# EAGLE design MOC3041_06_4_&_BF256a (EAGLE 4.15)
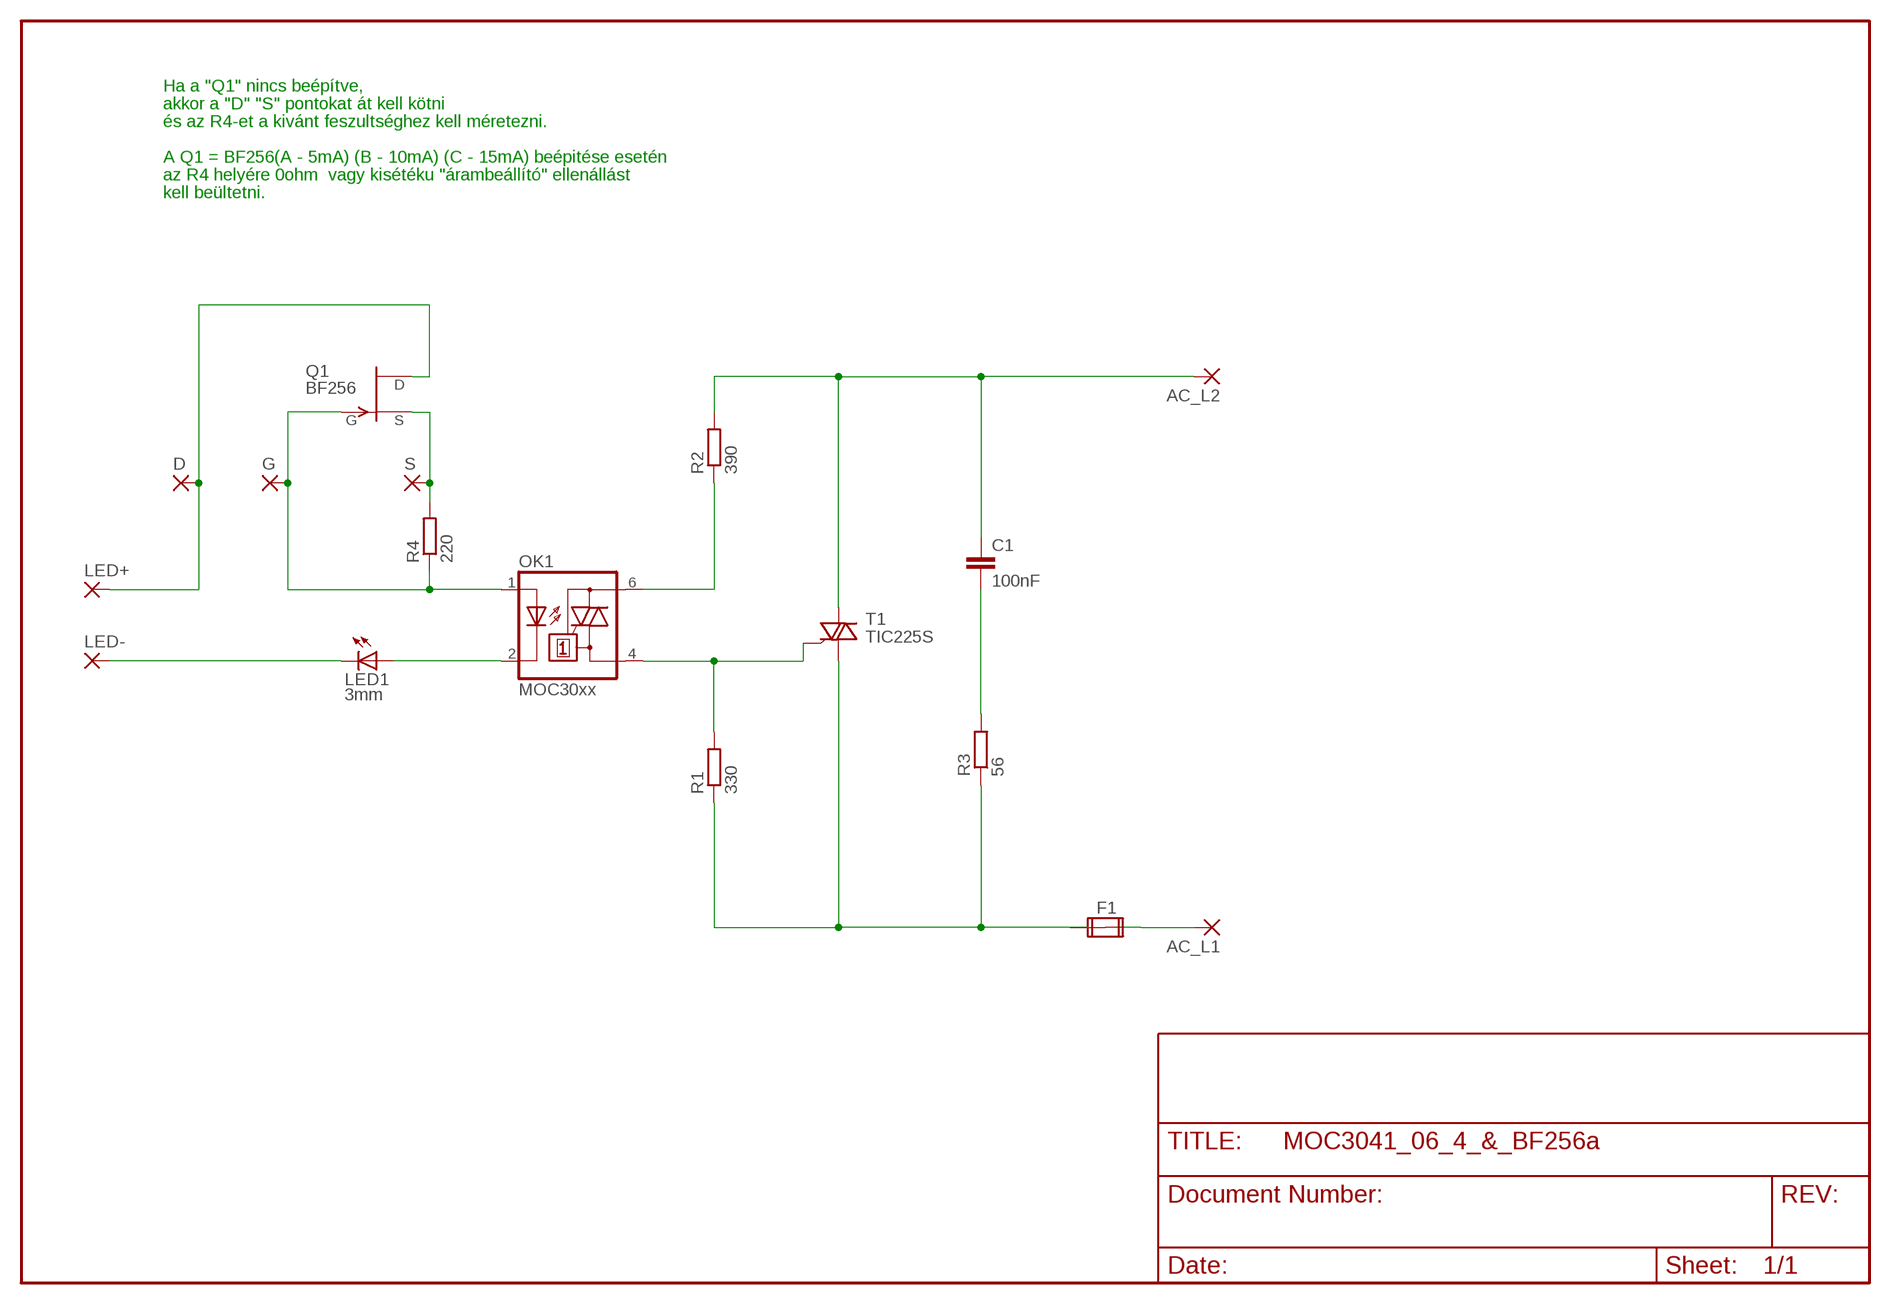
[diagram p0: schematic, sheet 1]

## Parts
AC_L1  3,17/1,1  [3,17/1,1]
AC_L2  3,17/1,1  [3,17/1,1]
C1  100nF  C-EU150-072X183  [C150-072X183]
D  2,54/0,8  [2,54/0,8]
F1  FUSE2P  [FUSE1]
G  2,54/0,8  [2,54/0,8]
LED1  3mm  LED3MM  [LED3MM]
LED+  3,17/1,1  [3,17/1,1]
LED-  3,17/1,1  [3,17/1,1]
OK1  MOC30xx  IL410  [DIL06]
Q1  BF256  [TO92]
R1  330  R-EU_0207/7  [0207/7]
R2  390  R-EU_0207/7  [0207/7]
R3  56  R-EU_0207/7  [0207/7]
R4  220  R-EU_0207/7  [0207/7]
S  2,54/0,8  [2,54/0,8]
T1  TIC225S  [TO220DS]

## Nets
N$2: C1.2 R3.2
N$4: OK1.6(A2) R2.1
N$5: OK1.4(A1) R1.2 T1.G
N$6: G.1(P) OK1.1(A) Q1.3(G) R4.1
N$7: Q1.2(S) R4.2 S.1(P)
N$8: LED1.A OK1.2(C)
N$9: LED1.K(C) LED-.1(P)
N$10: AC_L1.1(P) F1.2A F1.2B
N$11: F1.1A F1.1B R1.1 R3.1 T1.A1
N$15: D.1(P) LED+.1(P) Q1.1(D)
N$17: AC_L2.1(P) C1.1 R2.2 T1.A2

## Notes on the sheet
- Ha a "Q1" nincs beépítve,
- akkor a "D" "S" pontokat át kell kötni
- és az R4-et a kivánt feszultséghez kell méretezni.
- A Q1 = BF256(A - 5mA) (B - 10mA) (C - 15mA) beépitése esetén
- az R4 helyére 0ohm  vagy kisétéku "árambeállító" ellenállást
- kell beültetni.

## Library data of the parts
AC_L1 AC_L2 LED+ LED- = wirepad:3,17/1,1: THROUGH-HOLE PAD
C1 = rcl:C-EU: CAPACITOR, European symbol
D G S = wirepad:2,54/0,8: THROUGH-HOLE PAD
F1 = special:FUSE2P: FUSE 5 x 20 mm
LED1 = led:LED: LED
OK1 = optocoupler:IL410: SIEMENS OPTO COUPLER
Q1 = transistor-fet:BF256: N-Channel Junction FET
R1-R4 = rcl:R-EU_: RESISTOR, European symbol
T1 = triac:TIC225S: TRIAC

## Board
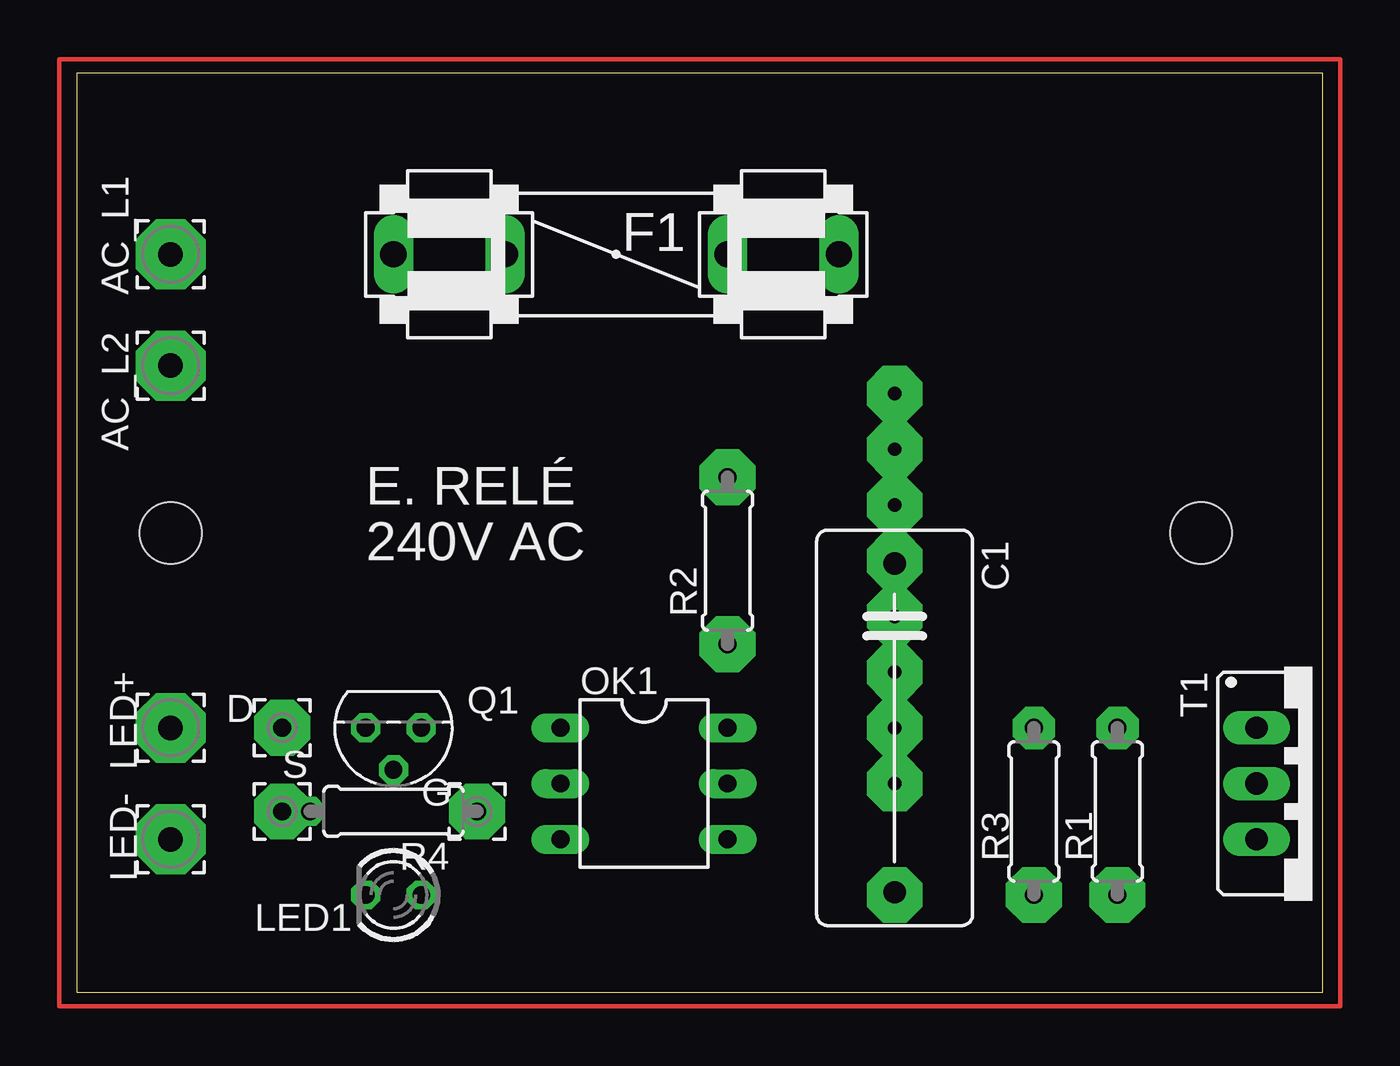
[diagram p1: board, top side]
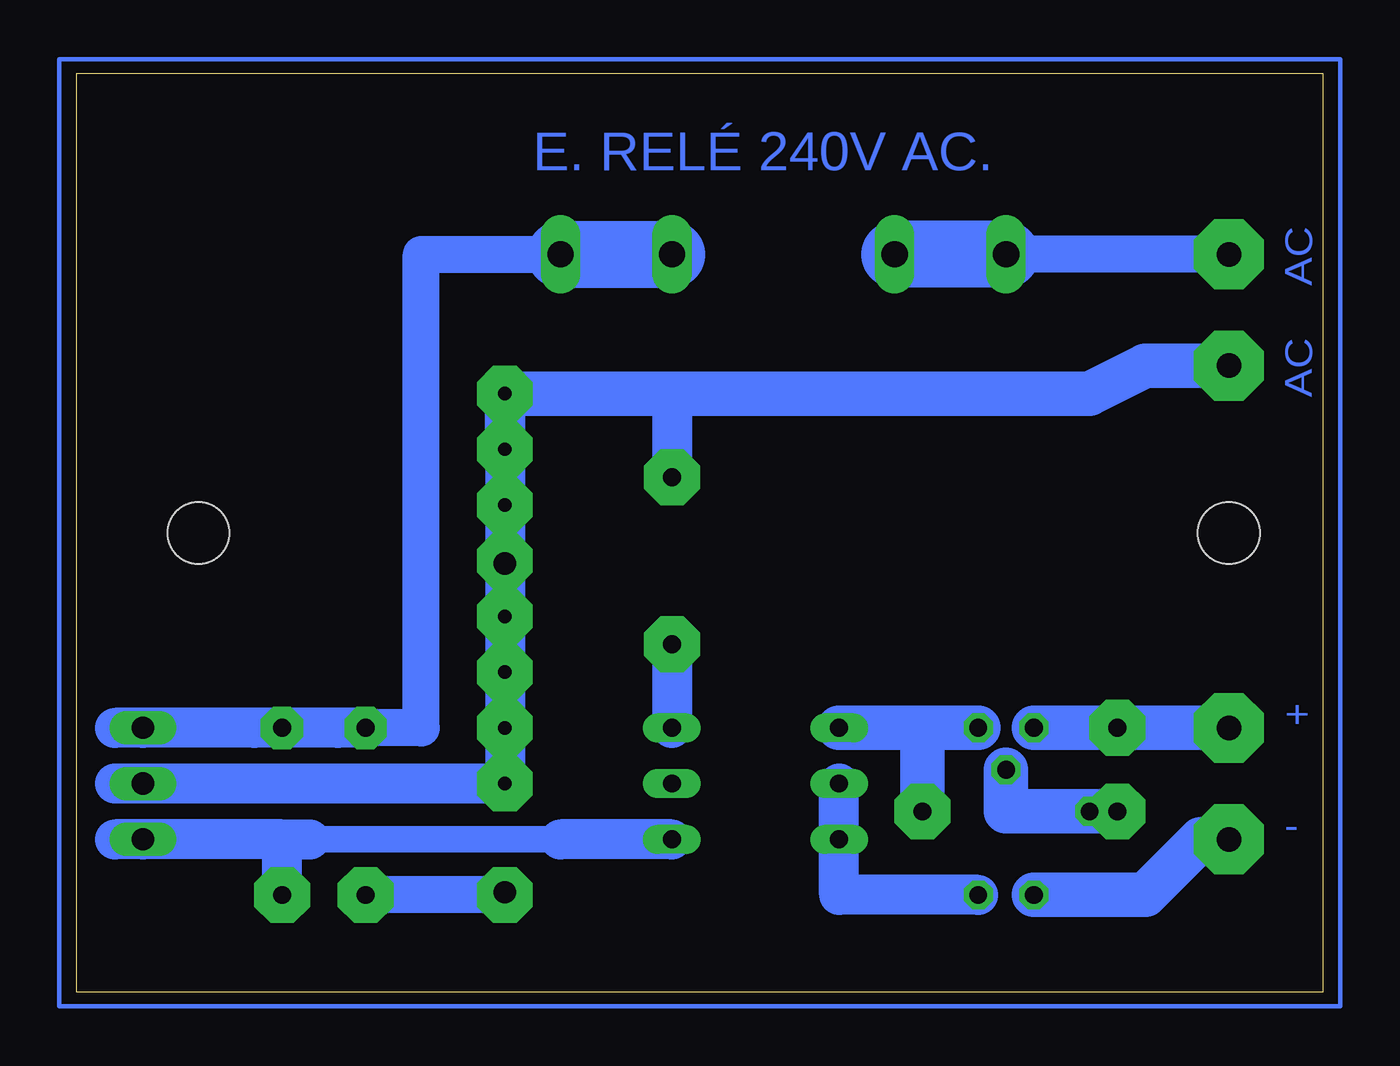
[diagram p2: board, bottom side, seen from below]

Size 56.82 x 41.9 mm. Coordinates in mm from the lower left corner, seen from the top.
Outline: 0,0 56.82,0 56.82,41.9 0,41.9 0,0
Copper layers (1*16): Top 0.035mm / dielectric 1.5mm / Bottom 0.035mm
Design rules "default": minimum track width 10mil, minimum drill 24mil, track to track 8mil, track to pad 8mil, pad to pad 8mil, via to via 8mil, smd to smd 8mil, copper to edge 40mil, drill to drill 8mil, minimum pad ring 10mil, minimum via ring 8mil, stop-mask expansion 4mil, vias tented up to drill 0mil, thermal gap 10mil
Holes 2.8 mm at 4.28,20.95 51.27,20.95

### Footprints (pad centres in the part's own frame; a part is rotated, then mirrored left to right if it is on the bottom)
3,17/1,1 = drill 1.118 pad 3.175 octagon: 1 0,0
C150-072X183 = drill 1.016 octagon: 1 -7.493,0; 2 7.493,0
2,54/0,8 = drill 0.813 pad 2.54 octagon: 1 0,0
FUSE1 = drill 1.194 long: 1A -10.16,0; 1B -5.08,0; 2A 10.16,0; 2B 5.08,0
LED3MM = drill 0.813 octagon: A -1.27,0; K 1.27,0
DIL06 = drill 0.813 long: 1 -2.54,-3.81; 2 0,-3.81; 3 2.54,-3.81; 4 2.54,3.81; 5 0,3.81; 6 -2.54,3.81
TO92 = drill 0.813 octagon: 1 1.27,0; 2 0,1.905; 3 -1.27,0
0207/7 = drill 0.813 octagon: 1 -3.81,0; 2 3.81,0
TO220DS = drill 1.016 long: A1 -2.54,-2.54; A2 0,-2.54; G 2.54,-2.54

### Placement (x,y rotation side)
AC_L1  4.28,33.65 90 top
AC_L2  4.28,28.57 270 top
C1  37.3,12.06 270 top
D  9.36,12.06 0 top
F1  24.6,33.65 180 top
G  18.25,8.25 0 top
LED1  14.44,4.44 180 top
LED+  4.28,12.06 0 top
LED-  4.28,6.98 0 top
OK1  25.87,9.52 270 top
Q1  14.44,12.06 180 top
R1  47.46,8.25 270 top
R2  29.68,19.68 90 top
R3  43.65,8.25 270 top
R4  14.44,8.25 180 top
S  9.36,8.25 0 top
T1  56.35,9.52 270 top

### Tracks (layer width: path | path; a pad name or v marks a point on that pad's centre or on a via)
N$1  (via drill 0.61 pad 2.54)
  other vias: 37.3,19.68
N$2  (via drill 0.61 pad 2.54)
  Bottom 0.254: C1.2 v37.3,4.44
  Bottom 1.676: v37.3,4.44 R3.2
N$3  (via drill 0.61 pad 2.54)
  other vias: 4.28,20.95
N$4
  Bottom 1.829: R2.1 OK1.6
N$5
  Bottom 1.219: 46.19,6.98 34.76,6.98
  Bottom 1.829: 55.08,6.98 T1.G 47.46,6.98 | OK1.4 34.76,6.98 | R1.2 47.46,6.98 | 47.46,6.98 46.19,6.98
N$6
  Bottom 2.032: 18.25,12.06 Q1.3 | 18.25,12.06 OK1.1 | G.1 18.25,12.06
N$7
  Bottom 2.032: Q1.2 14.44,8.25 R4.2 S.1
N$8
  Bottom 1.829: OK1.2 22.06,4.44 LED1.A
N$9
  Bottom 2.032: LED-.1 5.55,6.98 8.09,4.44 LED1.K
N$10
  Bottom 0.254: F1.2B F1.2A AC_L1.1
  Bottom 1.676: AC_L1.1 F1.2A F1.2B
  Bottom 3.048: F1.2A F1.2B
N$11  (via drill 0.61 pad 1.93)
  Bottom 0.254: F1.1A F1.1B
  Bottom 1.676: F1.1B F1.1A 41.11,33.65 41.11,12.06 R3.1
  Bottom 1.829: 55.08,12.06 T1.A1 R1.1 44.92,12.06 | R3.1 44.92,12.06 | 44.92,12.06 48.73,12.06
  Bottom 3.048: F1.1A F1.1B
  other vias: 43.65,12.06 47.46,12.06
N$12  (via drill 0.61 pad 2.54)
  other vias: 51.27,20.95
N$13  (via drill 0.61 pad 2.54)
  other vias: 47.46,4.44
N$14  (via drill 0.61 pad 2.54)
  other vias: 43.65,4.44
N$15
  Bottom 2.032: LED+.1 D.1 Q1.1
N$16  (via drill 0.61 pad 2.54)
  Bottom 0.61: v37.3,22.22 v37.3,24.76 v37.3,22.22 | v37.3,22.22 v37.3,17.14 v37.3,14.6 v37.3,12.06 v37.3,9.52
  Bottom 1.829: v29.68,23.49 29.68,27.3 v37.3,27.3 v37.3,24.76
N$17
  Bottom 1.829: 55.08,9.52 T1.A2 37.3,9.52 C1.1 37.3,27.3 | 29.68,27.3 R2.2
  Bottom 2.032: C1.1 37.3,19.68 | AC_L2.1 8.09,28.57 10.63,27.3 29.68,27.3 37.3,27.3
N$18
  Bottom 0.203: 57.62,-0.64 57.62,42.54 -0.8,42.54 -0.8,-0.64 57.62,-0.64
N$19
  Top 0.203: -0.8,42.54 57.62,42.54 57.62,-0.64 -0.8,-0.64 -0.8,42.54
N$20  (via drill 0.61 pad 2.54)
  other vias: 29.68,15.87

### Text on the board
Bottom: E. RELÉ 240V AC. | AC | AC | + | -
tPlace: E. RELÉ | 240V AC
